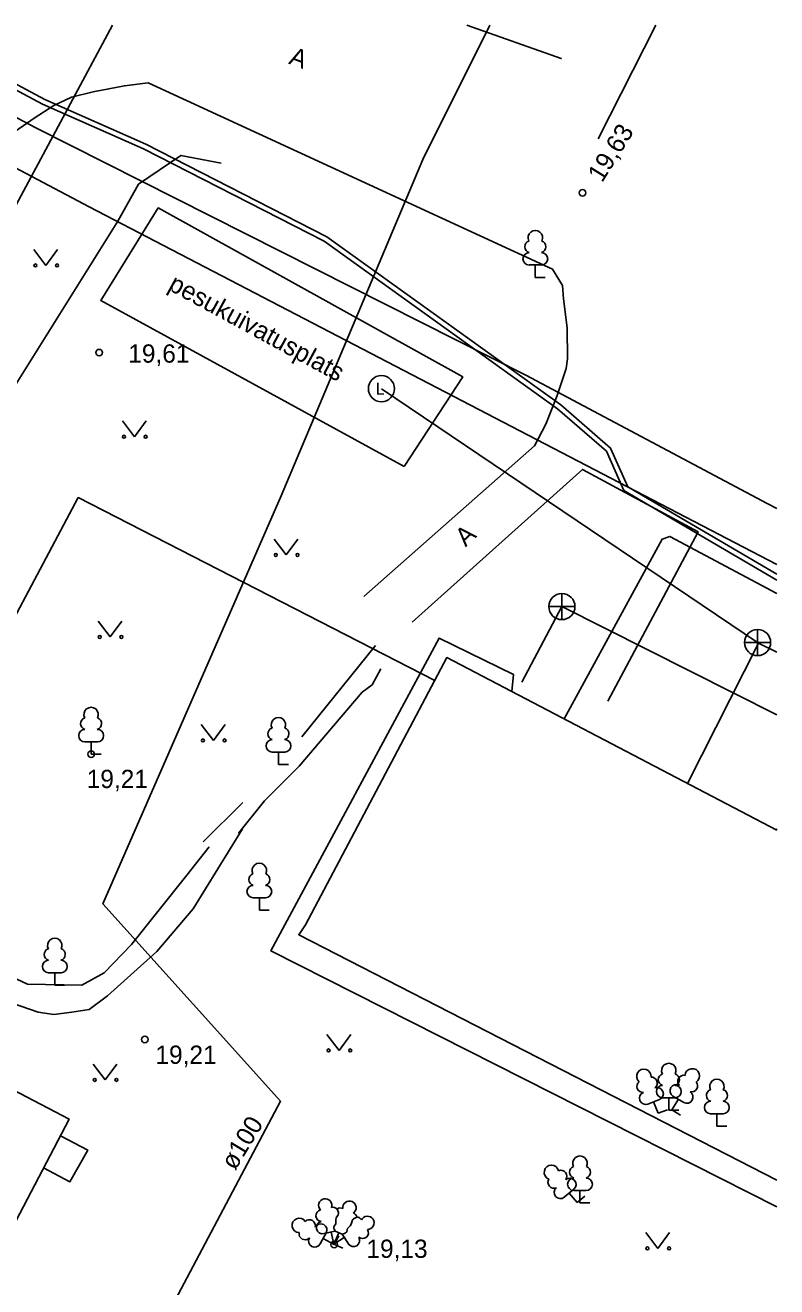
# Model space of a CAD drawing. Extents: x 713540 to 713867, y 6589774 to 6590061.
# Drawn here: x 713837.91 to 713866.67, y 6590012.33 to 6590060.64 of the extents above; entities that cross this region are included whole.
import ezdxf

# ---------------------------------------------------------------- set-up
doc = ezdxf.new("R2010")
doc.units = 0
for name, color, linetype in [('AED', 7, 'Continuous'), ('HALJASTUS', 7, 'Continuous'), ('HOONE', 7, 'Continuous'), ('HOONEDET', 7, 'Continuous'), ('KAEV', 7, 'Continuous'), ('KKAEV', 7, 'Continuous'), ('KORGUS', 7, 'Continuous'), ('KTRASS', 7, 'Continuous'), ('MPKAABEL', 7, 'Continuous'), ('PUU', 7, 'Continuous'), ('RAJATIS', 7, 'Continuous'), ('SKTRASS', 7, 'Continuous'), ('TEE', 7, 'Continuous'), ('TORU NR', 7, 'Continuous'), ('TTRASS', 7, 'Continuous')]:
    doc.layers.add(name, color=color, linetype=linetype)

msp = doc.modelspace()

# ---------------------------------------------------------------- linework, layer by layer
at = {"layer": 'AED'}
msp.add_lwpolyline([(713852.409, 6590043.742), (713854.654, 6590047.167), (713842.999, 6590053.64), (713840.801, 6590050.1), (713852.409, 6590043.742)], dxfattribs=at)
at = {"layer": 'HALJASTUS'}
for p, q in [((713838.237, 6590052.047), (713838.7, 6590051.44)), ((713838.7, 6590051.44), (713839.146, 6590052.047)), ((713841.627, 6590045.487), (713842.09, 6590044.88)), ((713842.09, 6590044.88), (713842.536, 6590045.487)), ((713847.437, 6590040.957), (713847.9, 6590040.35)), ((713847.9, 6590040.35), (713848.346, 6590040.957)), ((713840.697, 6590037.817), (713841.16, 6590037.21)), ((713841.16, 6590037.21), (713841.606, 6590037.817)), ((713844.647, 6590033.857), (713845.11, 6590033.25)), ((713845.11, 6590033.25), (713845.556, 6590033.857)), ((713849.457, 6590021.987), (713849.92, 6590021.38)), ((713849.92, 6590021.38), (713850.366, 6590021.987)), ((713840.507, 6590020.857), (713840.97, 6590020.25)), ((713840.97, 6590020.25), (713841.416, 6590020.857)), ((713861.657, 6590014.407), (713862.12, 6590013.8)), ((713862.12, 6590013.8), (713862.566, 6590014.407))]:
    msp.add_line(p, q, dxfattribs=at)
for points in [[(713845.41, 6590055.36), (713843.87, 6590055.65), (713842.25, 6590054.55), (713841.45, 6590053.13), (713837.43, 6590046.7)], [(713851.32, 6590036.89), (713848.5, 6590033.39)], [(713837.04, 6590023.32), (713838.41, 6590022.85), (713839, 6590022.76), (713839.69, 6590022.85), (713840.35, 6590022.95), (713841.06, 6590023.47), (713842.95, 6590025.17), (713844.33, 6590026.8), (713846.22, 6590029.86), (713846.08, 6590029.71), (713847.07, 6590030.94), (713848.39, 6590032.27), (713850.81, 6590035.1), (713851.19, 6590035.38), (713851.52, 6590035.99)], [(713844.72, 6590029.37), (713846.24, 6590030.87)], [(713844.95, 6590029.18), (713844.1, 6590028.09), (713841.97, 6590025.44), (713840.93, 6590024.35), (713840.08, 6590023.88), (713838, 6590023.92), (713836.06, 6590024.82), (713833.26, 6590026.53), (713831.14, 6590028.14)]]:
    msp.add_lwpolyline(points, dxfattribs=at)
for centre in [(713838.299, 6590051.44), (713839.128, 6590051.44), (713841.689, 6590044.88), (713842.518, 6590044.88), (713847.499, 6590040.35), (713848.328, 6590040.35), (713840.759, 6590037.21), (713841.588, 6590037.21), (713844.709, 6590033.25), (713845.538, 6590033.25), (713849.519, 6590021.38), (713850.348, 6590021.38), (713840.569, 6590020.25), (713841.398, 6590020.25), (713861.719, 6590013.8), (713862.548, 6590013.8)]:
    msp.add_circle(centre, 0.055, dxfattribs=at)
at = {"layer": 'HOONE'}
for points in [[(713841.243, 6590060.636), (713828.56, 6590036.98)], [(713855.691, 6590060.636), (713853.13, 6590055.49)], [(713853.13, 6590055.49), (713847.71, 6590042.61), (713840.88, 6590026.99), (713847.68, 6590019.43), (713836.38, 6589998.1), (713820.11, 6589968.4), (713812.16, 6589957.32), (713804.57, 6589946.51), (713791.35, 6589928.27), (713785.88, 6589931.15), (713778.18, 6589915.27), (713769.3, 6589896.72), (713774.33, 6589893.89), (713767.85, 6589880.54), (713761.86, 6589868.49), (713755.914, 6589856.728), (713753.12, 6589851.2), (713744.71, 6589834.75), (713742.63, 6589834)], [(713866.671, 6590038.88), (713862.58, 6590041.06), (713862.28, 6590040.96), (713858.54, 6590034.07)], [(713866.671, 6590016.416), (713848.38, 6590025.81), (713848.63, 6590026.19), (713854.05, 6590036.42), (713866.671, 6590029.817)], [(713826.57, 6590025.56), (713823.22, 6590019.15), (713836.24, 6590012.35), (713839.59, 6590018.75), (713826.57, 6590025.56)]]:
    msp.add_lwpolyline(points, dxfattribs=at)
at = {"layer": 'HOONEDET'}
for points in [[(713856.53, 6590035.12), (713856.6, 6590035.77), (713853.75, 6590037.17), (713847.31, 6590025.19), (713866.671, 6590015.388)], [(713838.61, 6590016.88), (713839.62, 6590016.35), (713840.3, 6590017.56), (713839.26, 6590018.11)]]:
    msp.add_lwpolyline(points, dxfattribs=at)
at = {"layer": 'KAEV'}
msp.add_circle((713851.54, 6590046.72), 0.5, dxfattribs=at)
at = {"layer": 'KKAEV'}
for p, q in [((713865.937, 6590036.497), (713865.937, 6590037.497)), ((713865.437, 6590036.997), (713866.437, 6590036.997))]:
    msp.add_line(p, q, dxfattribs=at)
msp.add_circle((713865.937, 6590036.997), 0.5, dxfattribs=at)
at = {"layer": 'KORGUS'}
for centre in [(713859.24, 6590054.22), (713840.74, 6590048.1), (713840.43, 6590032.72), (713842.49, 6590021.8), (713849.73, 6590013.95)]:
    msp.add_circle(centre, 0.125, dxfattribs=at)
at = {"layer": 'KTRASS'}
for p, q in [((713858.447, 6590037.874), (713858.447, 6590038.874)), ((713857.947, 6590038.374), (713858.947, 6590038.374))]:
    msp.add_line(p, q, dxfattribs=at)
for points in [[(713858.447, 6590038.374), (713856.914, 6590035.483)], [(713858.447, 6590038.374), (713866.671, 6590034.225)], [(713866.671, 6590029.862), (713866.652, 6590029.826)]]:
    msp.add_lwpolyline(points, dxfattribs=at)
msp.add_circle((713858.447, 6590038.374), 0.5, dxfattribs=at)
at = {"layer": 'MPKAABEL'}
for points in [[(713832.9, 6590060.636), (713833.174, 6590060.499), (713838.567, 6590057.617), (713842.439, 6590055.897), (713849.346, 6590052.366), (713858.277, 6590045.944), (713860.149, 6590044.325), (713860.818, 6590042.823), (713866.671, 6590039.39)], [(713833.342, 6590060.636), (713838.655, 6590057.797), (713842.525, 6590056.077), (713849.45, 6590052.538), (713858.401, 6590046.102), (713860.313, 6590044.447), (713860.974, 6590042.963), (713866.671, 6590039.622)], [(713866.671, 6590042.131), (713866.3, 6590042.32), (713857.07, 6590047.23), (713838.31, 6590056.71), (713834.222, 6590058.865)], [(713866.671, 6590039.989), (713840.35, 6590053.68), (713833.306, 6590057.414)]]:
    msp.add_lwpolyline(points, dxfattribs=at)
at = {"layer": 'PUU'}
for p, q in [((713857.67, 6590051.455), (713857.19, 6590051.455)), ((713857.43, 6590050.98), (713857.43, 6590051.455)), ((713857.81, 6590050.98), (713857.43, 6590050.98)), ((713840.67, 6590033.195), (713840.19, 6590033.195)), ((713840.43, 6590032.72), (713840.43, 6590033.195)), ((713840.81, 6590032.72), (713840.43, 6590032.72)), ((713847.84, 6590032.805), (713847.36, 6590032.805)), ((713847.6, 6590032.33), (713847.6, 6590032.805)), ((713847.98, 6590032.33), (713847.6, 6590032.33)), ((713847.11, 6590027.225), (713846.63, 6590027.225)), ((713846.87, 6590026.75), (713846.87, 6590027.225)), ((713847.25, 6590026.75), (713846.87, 6590026.75)), ((713839.28, 6590024.355), (713838.8, 6590024.355)), ((713839.04, 6590023.88), (713839.04, 6590024.355)), ((713839.42, 6590023.88), (713839.04, 6590023.88)), ((713862.183, 6590019.5), (713861.735, 6590019.327)), ((713862.13, 6590018.97), (713861.959, 6590019.413)), ((713862.78, 6590019.565), (713862.3, 6590019.565)), ((713862.54, 6590019.09), (713862.54, 6590019.565)), ((713862.66, 6590019.1), (713862.904, 6590019.508)), ((713863.11, 6590019.385), (713862.698, 6590019.631)), ((713862.485, 6590019.107), (713862.13, 6590018.97)), ((713862.92, 6590019.09), (713862.54, 6590019.09)), ((713862.986, 6590018.905), (713862.66, 6590019.1)), ((713864.62, 6590018.955), (713864.14, 6590018.955)), ((713864.38, 6590018.48), (713864.38, 6590018.955)), ((713864.76, 6590018.48), (713864.38, 6590018.48)), ((713858.907, 6590016.068), (713858.54, 6590015.758)), ((713859.38, 6590016.015), (713858.9, 6590016.015)), ((713859.14, 6590015.54), (713859.14, 6590016.015)), ((713859.03, 6590015.55), (713858.724, 6590015.913)), ((713859.32, 6590015.795), (713859.03, 6590015.55)), ((713859.52, 6590015.54), (713859.14, 6590015.54)), ((713849.428, 6590014.388), (713849.198, 6590013.967)), ((713849.73, 6590013.95), (713849.313, 6590014.177)), ((713849.337, 6590014.362), (713849.768, 6590014.456)), ((713849.72, 6590013.96), (713849.618, 6590014.422)), ((713849.72, 6590013.96), (713849.906, 6590014.397)), ((713849.72, 6590013.96), (713850.121, 6590014.213)), ((713849.912, 6590014.284), (713849.73, 6590013.95)), ((713849.768, 6590014.456), (713850.04, 6590014.34)), ((713850.04, 6590014.34), (713850.275, 6590013.973)), ((713850.07, 6590013.811), (713849.72, 6590013.96))]:
    msp.add_line(p, q, dxfattribs=at)
for points in [[(713849.846, 6590015.306), (713849.9, 6590015.172), (713849.902, 6590015.138), (713849.88, 6590015.088), (713849.831, 6590015.011), (713849.814, 6590014.969), (713849.801, 6590014.888), (713849.802, 6590014.789), (713849.794, 6590014.744), (713849.771, 6590014.705), (713849.732, 6590014.651), (713849.72, 6590014.623), (713849.723, 6590014.578), (713849.734, 6590014.541), (713849.768, 6590014.456)], [(713850.602, 6590014.999), (713850.47, 6590014.928), (713850.445, 6590014.907), (713850.423, 6590014.856), (713850.401, 6590014.767), (713850.388, 6590014.724), (713850.339, 6590014.658), (713850.266, 6590014.591), (713850.24, 6590014.554), (713850.227, 6590014.51), (713850.215, 6590014.445), (713850.203, 6590014.417), (713850.169, 6590014.388), (713850.134, 6590014.37), (713850.044, 6590014.338)]]:
    msp.add_lwpolyline(points, dxfattribs=at)
for centre, radius, start, end in [((713857.43, 6590052.5), 0.277, 332.5799, 207.4201), ((713857.26, 6590052.153), 0.233, 109.0217, 253.1415), ((713857.6, 6590052.153), 0.233, 286.8508, 70.9859), ((713857.193, 6590051.692), 0.238, 90.0016, 269.3953), ((713857.667, 6590051.692), 0.238, 270.6047, 89.9984), ((713840.43, 6590034.24), 0.277, 332.5799, 207.4201), ((713840.26, 6590033.893), 0.233, 109.0217, 253.1415), ((713840.6, 6590033.893), 0.233, 286.8508, 70.9859), ((713847.6, 6590033.85), 0.277, 332.5799, 207.4201), ((713840.193, 6590033.432), 0.238, 90.0016, 269.3953), ((713840.667, 6590033.432), 0.238, 270.6047, 89.9984), ((713847.43, 6590033.503), 0.233, 109.0217, 253.1415), ((713847.77, 6590033.503), 0.233, 286.8508, 70.9859), ((713847.363, 6590033.042), 0.238, 90.0016, 269.3953), ((713847.837, 6590033.042), 0.238, 270.6047, 89.9984), ((713846.87, 6590028.27), 0.277, 332.5799, 207.4201), ((713846.7, 6590027.923), 0.233, 109.0217, 253.1415), ((713847.04, 6590027.923), 0.233, 286.8508, 70.9859), ((713846.633, 6590027.462), 0.238, 90.0016, 269.3953), ((713847.107, 6590027.462), 0.238, 270.6047, 89.9984), ((713839.04, 6590025.4), 0.277, 332.5799, 207.4201), ((713838.87, 6590025.053), 0.233, 109.0217, 253.1415), ((713839.21, 6590025.053), 0.233, 286.8508, 70.9859), ((713838.803, 6590024.592), 0.238, 90.0016, 269.3953), ((713839.277, 6590024.592), 0.238, 270.6047, 89.9984), ((713862.54, 6590020.61), 0.277, 332.5799, 207.4201), ((713861.583, 6590020.388), 0.277, 353.6678, 228.508), ((713861.867, 6590020.125), 0.233, 307.9387, 92.0738), ((713862.37, 6590020.263), 0.233, 109.0217, 253.1415), ((713862.71, 6590020.263), 0.233, 286.8508, 70.9859), ((713863.115, 6590020.194), 0.233, 78.1751, 222.2949), ((713863.439, 6590020.405), 0.277, 301.7333, 176.5735), ((713861.549, 6590020.003), 0.233, 130.1096, 274.2294), ((713862.095, 6590019.72), 0.238, 291.6926, 111.0863), ((713862.303, 6590019.802), 0.238, 90.0016, 269.3953), ((713862.821, 6590019.833), 0.238, 59.155, 238.5487), ((713862.777, 6590019.802), 0.238, 270.6047, 89.9984), ((713863.407, 6590020.019), 0.233, 256.0042, 40.1393), ((713864.21, 6590019.653), 0.233, 109.0217, 253.1415), ((713864.38, 6590020), 0.277, 332.5799, 207.4201), ((713864.55, 6590019.653), 0.233, 286.8508, 70.9859), ((713861.652, 6590019.549), 0.238, 111.0895, 290.4832), ((713863.229, 6590019.59), 0.238, 239.7581, 59.1518), ((713864.143, 6590019.192), 0.238, 90.0016, 269.3953), ((713864.617, 6590019.192), 0.238, 270.6047, 89.9984), ((713858.049, 6590016.711), 0.277, 12.7532, 247.5934), ((713858.97, 6590016.713), 0.233, 109.0217, 253.1415), ((713859.14, 6590017.06), 0.277, 332.5799, 207.4201), ((713859.31, 6590016.713), 0.233, 286.8508, 70.9859), ((713858.144, 6590016.336), 0.233, 149.195, 293.3148), ((713858.404, 6590016.556), 0.233, 327.0241, 111.1592), ((713858.752, 6590016.248), 0.238, 310.778, 130.1717), ((713858.903, 6590016.252), 0.238, 90.0016, 269.3953), ((713859.377, 6590016.252), 0.238, 270.6047, 89.9984), ((713858.389, 6590015.941), 0.238, 130.1749, 309.5686), ((713849.393, 6590015.444), 0.256, 102.436, 223.4506), ((713849.393, 6590015.444), 0.256, 341.4189, 102.4335), ((713850.316, 6590015.358), 0.256, 66.8983, 187.9129), ((713850.316, 6590015.358), 0.256, 305.8812, 66.8958), ((713849.255, 6590015.05), 0.224, 102.3637, 265.432), ((713849.696, 6590015.171), 0.202, 42.1353, 107.6383), ((713849.968, 6590015.145), 0.202, 61.6935, 127.1965), ((713850.404, 6590014.959), 0.202, 11.2827, 72.1006), ((713850.595, 6590014.797), 0.202, 27.2143, 88.0322), ((713851.003, 6590014.775), 0.256, 32.4191, 153.4337), ((713848.396, 6590014.678), 0.277, 33.9683, 268.8085), ((713848.782, 6590014.661), 0.233, 348.2392, 132.3743), ((713849.218, 6590014.5), 0.238, 331.9931, 151.3868), ((713849.288, 6590014.594), 0.237, 102.4347, 282.4337), ((713850.82, 6590014.399), 0.224, 229.4206, 32.4889), ((713851.003, 6590014.775), 0.256, 271.402, 32.4166), ((713848.619, 6590014.362), 0.233, 170.4102, 314.53), ((713848.991, 6590014.083), 0.238, 151.39, 330.7837), ((713850.474, 6590014.101), 0.237, 212.4189, 32.4178)]:
    msp.add_arc(centre, radius, start, end, dxfattribs=at)
at = {"layer": 'SKTRASS'}
for points in [[(713865.97, 6590036.98), (713851.54, 6590046.71)], [(713863.26, 6590031.6), (713865.97, 6590036.98)], [(713866.671, 6590036.623), (713865.97, 6590036.98)]]:
    msp.add_lwpolyline(points, dxfattribs=at)
at = {"layer": 'TEE'}
for points in [[(713854.815, 6590060.636), (713858.42, 6590059.359), (713854.815, 6590060.636)], [(713862.045, 6590060.636), (713859.842, 6590056.29)], [(713830.359, 6590027.27), (713828.03, 6590028.451), (713825.945, 6590030.859), (713825.312, 6590034.147), (713828.441, 6590040), (713833.34, 6590049.077), (713837.532, 6590056.579), (713837.534, 6590056.582), (713838.257, 6590057.083), (713839.007, 6590057.56), (713839.678, 6590057.883), (713840.511, 6590058.091), (713841.702, 6590058.32), (713842.617, 6590058.429), (713858.089, 6590051.299), (713858.467, 6590050.667), (713858.503, 6590050.161), (713858.645, 6590049.048), (713858.665, 6590047.864), (713858.616, 6590047.494), (713858.27, 6590046.462), (713857.836, 6590045.357), (713857.405, 6590044.532), (713850.874, 6590038.76)], [(713860.205, 6590034.749), (713863.669, 6590041.234), (713859.233, 6590043.628), (713852.717, 6590037.774)]]:
    msp.add_lwpolyline(points, dxfattribs=at)
at = {"layer": 'TTRASS'}
msp.add_lwpolyline([(713853.59, 6590035.55), (713839.94, 6590042.55), (713835.67, 6590034.53), (713826.58, 6590039.27)], dxfattribs=at)

# ---------------------------------------------------------------- texts
at = {"layer": 'KAEV'}
msp.add_text('L', height=0.45, dxfattribs=at).set_placement((713851.326, 6590046.495))
at = {"layer": 'KORGUS'}
msp.add_text('19,63', height=0.7, rotation=58.0899, dxfattribs=at).set_placement((713859.986, 6590054.581))
for s, p in [('19,61', (713841.852, 6590047.715)), ('19,21', (713840.262, 6590031.425)), ('19,21', (713842.892, 6590020.865)), ('19,13', (713850.966, 6590013.435))]:
    msp.add_text(s, height=0.7, dxfattribs=at).set_placement(p)
at = {"layer": 'RAJATIS'}
msp.add_text('pesukuivatusplats', height=0.7, rotation=331.4431, dxfattribs=at).set_placement((713843.34, 6590050.53))
at = {"layer": 'TEE'}
for rotation, p in [(339.9397, (713847.96, 6590059.17)), (42.8455, (713854.76, 6590040.64))]:
    msp.add_text('A', height=0.7, rotation=rotation, dxfattribs=at).set_placement(p)
at = {"layer": 'TORU NR'}
msp.add_text('ø100', height=0.7, rotation=58.7707, dxfattribs=at).set_placement((713845.942, 6590016.754))

doc.saveas('drawing.dxf')
